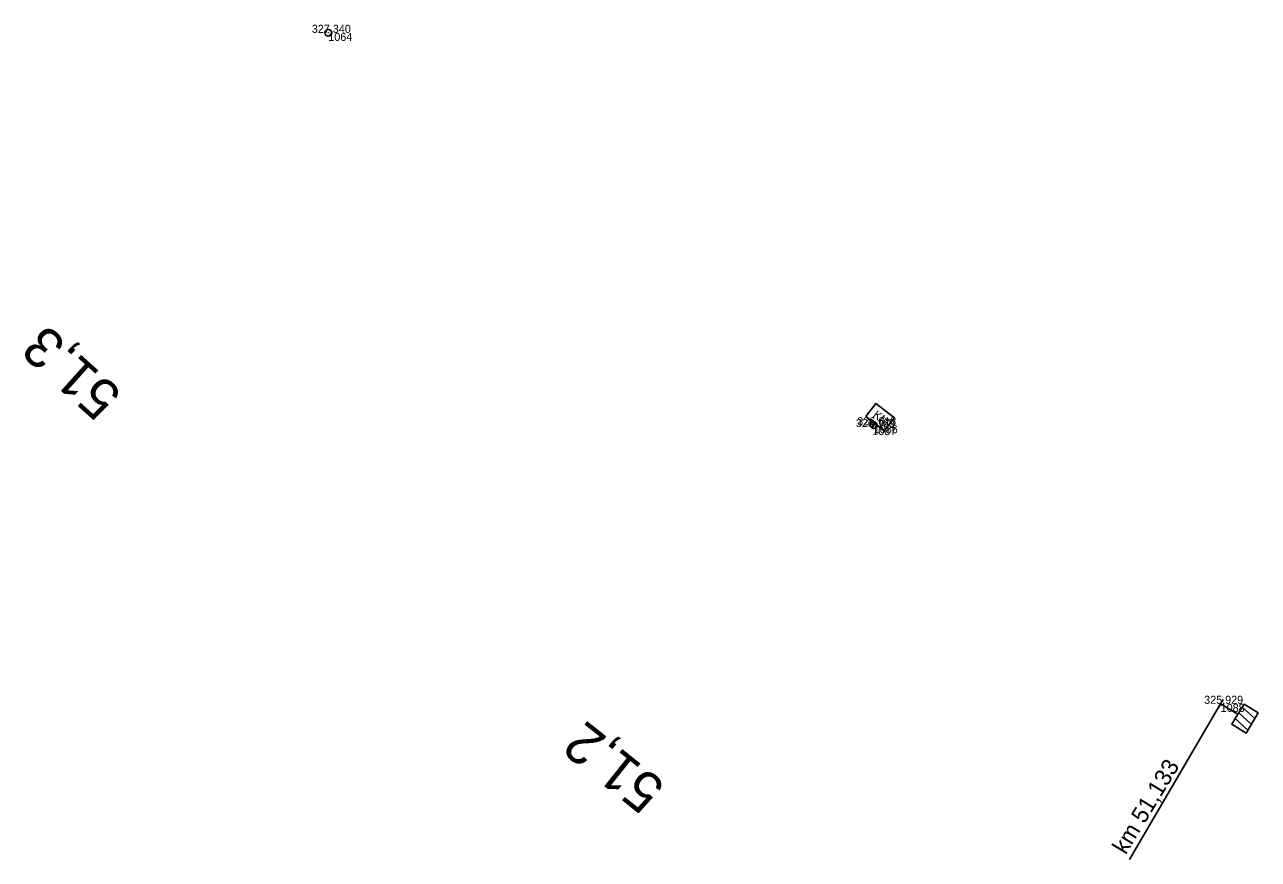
# Model space of a CAD drawing. Extents: x -661256 to -633155, y -1027786 to -1004130.
# Drawn here: x -638247.9 to -638064.1, y -1020970.7 to -1020846.3 of the extents above; entities that cross this region are included whole.
import ezdxf

# ---------------------------------------------------------------- set-up
doc = ezdxf.new("R2010")
doc.units = 0
for name, color, linetype in [('Vrstva 60', 7, 'Continuous'), ('Vrstva 61', 7, 'Continuous'), ('Vrstva 7', 7, 'Continuous')]:
    doc.layers.add(name, color=color, linetype=linetype)

msp = doc.modelspace()

# ---------------------------------------------------------------- linework, layer by layer
at = {"layer": 'Vrstva 60'}
for p, q in [((-638202.66, -1020847.52), (-638202.66, -1020847.52)), ((-638121.6, -1020906.27), (-638121.6, -1020906.27)), ((-638121.39, -1020906), (-638121.39, -1020906)), ((-638069.7, -1020947.52), (-638069.7, -1020947.52))]:
    msp.add_line(p, q, dxfattribs=at)
at = {"layer": 'Vrstva 7'}
for p, q in [((-638202.62, -1020847.55), (-638202.7, -1020847.49)), ((-638121.6, -1020906.27), (-638121.21, -1020905.78)), ((-638121.35, -1020906.03), (-638121.43, -1020905.97)), ((-638069.7, -1020947.52), (-638083.29, -1020970.7)), ((-638069.31, -1020946.88), (-638070.09, -1020948.16)), ((-638065.12, -1020950.58), (-638067, -1020948.86)), ((-638066.48, -1020948), (-638064.61, -1020949.73)), ((-638067.52, -1020949.71), (-638065.64, -1020951.44))]:
    msp.add_line(p, q, dxfattribs=at)
msp.add_lwpolyline([(-638122.59, -1020904.71), (-638121.06, -1020902.75), (-638118.31, -1020904.9), (-638119.84, -1020906.86)], close=True, dxfattribs=at)
msp.add_lwpolyline([(-638069.7, -1020947.52), (-638067.13, -1020949.07), (-638068.04, -1020950.57), (-638065.9, -1020951.87), (-638064.09, -1020948.87), (-638066.22, -1020947.58), (-638067.13, -1020949.07)], dxfattribs=at)
for centre in [(-638202.66, -1020847.52), (-638121.39, -1020906)]:
    msp.add_circle(centre, 0.5, dxfattribs=at)

# ---------------------------------------------------------------- texts
at = {"layer": 'Vrstva 60'}
for s, p in [('1064', (-638202.66, -1020848.72)), ('1087', (-638121.6, -1020907.47)), ('1086', (-638121.39, -1020907.2)), ('1088', (-638069.7, -1020948.72))]:
    msp.add_text(s, height=1.2, dxfattribs=at).set_placement(p)
at = {"layer": 'Vrstva 61'}
for s, p in [('327.340', (-638205.11, -1020847.52)), ('326.169', (-638124.05, -1020906.27)), ('326.618', (-638123.84, -1020906)), ('325.929', (-638072.15, -1020947.52))]:
    msp.add_text(s, height=1.2, dxfattribs=at).set_placement(p)
at = {"layer": 'Vrstva 7'}
for s, height, rotation, p in [('51,3', 6, 138.056, (-638233.15, -1020901.22)), ('KM', 1.247, 322.0295, (-638121.63, -1020904.67)), ('51,2', 6, 141.4808, (-638152.18, -1020959.58)), ('km 51,133', 2.5, 58.7663, (-638083.85, -1020970.11))]:
    msp.add_text(s, height=height, rotation=rotation, dxfattribs=at).set_placement(p)

doc.saveas('drawing.dxf')
